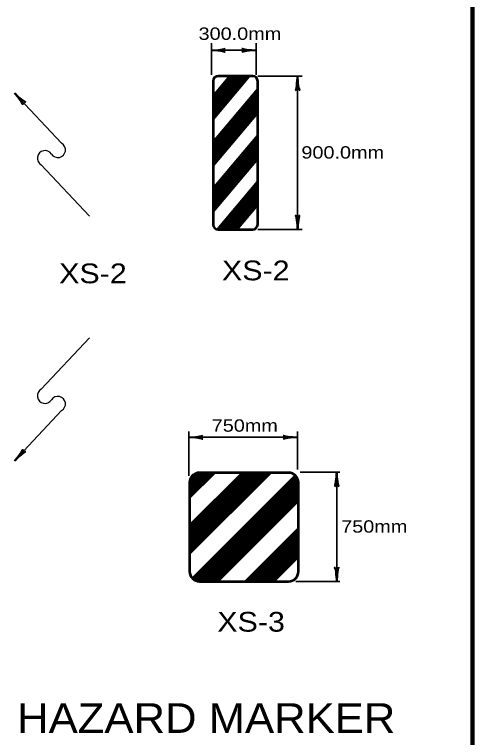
# Model space of a CAD drawing. Extents: x -1843 to -987, y 1073 to 1617.
# Drawn here: x -1105 to -993.8, y 1298.6 to 1474.2 of the extents above; entities that cross this region are included whole.
import ezdxf
from ezdxf.enums import TextEntityAlignment as Align

# ---------------------------------------------------------------- set-up
doc = ezdxf.new("R2010")
doc.units = 0
doc.header["$LTSCALE"] = 1.2
doc.layers.add('1', color=7, linetype='Continuous', lineweight=53)

msp = doc.modelspace()

# ---------------------------------------------------------------- linework, layer by layer
at = {"layer": '1', "lineweight": 158}
msp.add_line((-993.822, 1084.318), (-993.822, 1610.418), dxfattribs=at)
at = {"layer": '1', "lineweight": 13}
msp.add_line((-993.822, 1084.318), (-993.822, 1610.418), dxfattribs=at)
at = {"layer": '1', "lineweight": 35}
for p, q in [((-1057.149, 1459.516), (-1057.149, 1467.22)), ((-1046.35, 1459.516), (-1046.35, 1467.22)), ((-1057.284, 1465.455), (-1046.348, 1465.455)), ((-1045.947, 1459.178), (-1035.2, 1459.178)), ((-1036.297, 1459.178), (-1036.297, 1421.993)), ((-1045.947, 1421.978), (-1035.2, 1421.978)), ((-1062.693, 1372.873), (-1062.693, 1362.126)), ((-1036.293, 1372.873), (-1036.293, 1363.643)), ((-1062.774, 1371.497), (-1036.364, 1371.497)), ((-1035.674, 1363.034), (-1026.044, 1363.034)), ((-1026.785, 1363.039), (-1026.785, 1336.543)), ((-1036.748, 1336.504), (-1026.001, 1336.504))]:
    msp.add_line(p, q, dxfattribs=at)
at = {"layer": '1'}
for p, q in [((-1056.781, 1454.325), (-1052.713, 1459.172)), ((-1056.772, 1454.318), (-1052.705, 1459.165)), ((-1056.772, 1448.717), (-1048.005, 1459.165)), ((-1056.772, 1453.902), (-1052.356, 1459.165)), ((-1056.772, 1453.767), (-1052.243, 1459.165)), ((-1056.772, 1453.417), (-1051.949, 1459.165)), ((-1056.772, 1452.986), (-1051.587, 1459.165)), ((-1056.772, 1452.69), (-1051.339, 1459.165)), ((-1056.772, 1452.34), (-1051.045, 1459.165)), ((-1056.772, 1451.761), (-1050.56, 1459.165)), ((-1056.772, 1451.613), (-1050.435, 1459.165)), ((-1056.772, 1451.237), (-1050.12, 1459.165)), ((-1056.772, 1450.7), (-1049.669, 1459.165)), ((-1056.772, 1450.324), (-1049.353, 1459.165)), ((-1056.772, 1450.028), (-1049.105, 1459.165)), ((-1056.772, 1449.517), (-1048.676, 1459.165)), ((-1056.772, 1449.019), (-1048.258, 1459.165)), ((-1056.772, 1449.803), (-1048.916, 1459.165)), ((-1056.772, 1449.937), (-1049.029, 1459.165)), ((-1056.772, 1450.072), (-1049.142, 1459.165)), ((-1056.772, 1451.082), (-1049.989, 1459.165)), ((-1056.772, 1451.365), (-1050.227, 1459.165)), ((-1056.772, 1451.943), (-1050.712, 1459.165)), ((-1056.772, 1453.194), (-1051.762, 1459.165)), ((-1056.772, 1454.04), (-1052.472, 1459.165)), ((-1056.772, 1453.622), (-1052.121, 1459.165)), ((-1056.772, 1453.272), (-1051.827, 1459.165)), ((-1056.772, 1452.4), (-1051.096, 1459.165)), ((-1056.772, 1452.185), (-1050.915, 1459.165)), ((-1056.772, 1452.05), (-1050.802, 1459.165)), ((-1056.772, 1450.841), (-1049.787, 1459.165)), ((-1056.772, 1449.336), (-1048.524, 1459.165)), ((-1056.635, 1454.203), (-1052.568, 1459.05)), ((-1056.562, 1454.142), (-1052.347, 1459.165)), ((-1056.516, 1454.103), (-1052.449, 1458.95)), ((-1056.51, 1454.098), (-1052.258, 1459.165)), ((-1047.172, 1459.165), (-1055.572, 1459.165)), ((-1055.221, 1453.016), (-1050.062, 1459.165)), ((-1056.772, 1453.153), (-1052.131, 1458.683)), ((-1056.772, 1452.979), (-1052.045, 1458.611)), ((-1056.772, 1457.965), (-1056.772, 1423.165)), ((-1056.098, 1453.753), (-1052.031, 1458.6)), ((-1055.967, 1453.642), (-1051.9, 1458.489)), ((-1055.828, 1453.525), (-1051.76, 1458.372)), ((-1055.828, 1453.525), (-1051.76, 1458.372)), ((-1055.794, 1453.497), (-1051.727, 1458.345)), ((-1054.821, 1452.68), (-1050.753, 1457.528)), ((-1054.416, 1452.341), (-1050.348, 1457.188)), ((-1054.319, 1452.259), (-1050.251, 1457.106)), ((-1045.972, 1423.165), (-1045.972, 1457.965)), ((-1056.772, 1443.116), (-1045.972, 1455.987)), ((-1056.772, 1442.708), (-1045.972, 1455.579)), ((-1056.772, 1442.486), (-1045.972, 1455.357)), ((-1054.177, 1452.14), (-1050.109, 1456.987)), ((-1056.772, 1442.089), (-1045.972, 1454.96)), ((-1056.772, 1441.91), (-1045.972, 1454.781)), ((-1056.772, 1441.557), (-1045.972, 1454.428)), ((-1056.772, 1441.325), (-1045.972, 1454.196)), ((-1056.772, 1441.112), (-1045.972, 1453.983)), ((-1056.772, 1440.794), (-1045.972, 1453.665)), ((-1056.772, 1440.566), (-1045.972, 1453.437)), ((-1056.772, 1440.249), (-1045.972, 1453.12)), ((-1056.772, 1439.945), (-1045.972, 1452.816)), ((-1056.772, 1439.637), (-1045.972, 1452.508)), ((-1056.772, 1439.372), (-1045.972, 1452.243)), ((-1056.772, 1439.074), (-1045.972, 1451.945)), ((-1056.772, 1438.716), (-1045.972, 1451.587)), ((-1056.772, 1438.481), (-1045.972, 1451.352)), ((-1056.772, 1438.083), (-1045.972, 1450.954)), ((-1056.772, 1437.774), (-1045.972, 1450.645)), ((-1056.772, 1437.516), (-1045.972, 1450.387)), ((-1056.772, 1431.915), (-1045.972, 1444.786)), ((-1056.772, 1431.715), (-1045.972, 1444.586)), ((-1056.772, 1431.48), (-1045.972, 1444.351)), ((-1056.772, 1431.225), (-1045.972, 1444.096)), ((-1056.772, 1431.077), (-1045.972, 1443.948)), ((-1056.772, 1430.855), (-1045.972, 1443.726)), ((-1056.772, 1430.565), (-1045.972, 1443.436)), ((-1056.772, 1430.384), (-1045.972, 1443.255)), ((-1056.772, 1430.162), (-1045.972, 1443.033)), ((-1056.772, 1429.866), (-1045.972, 1442.737)), ((-1056.772, 1429.651), (-1045.972, 1442.522)), ((-1056.772, 1429.315), (-1045.972, 1442.186)), ((-1056.772, 1429.012), (-1045.972, 1441.883)), ((-1056.772, 1428.763), (-1045.972, 1441.634)), ((-1056.772, 1428.615), (-1045.972, 1441.486)), ((-1056.772, 1428.376), (-1045.972, 1441.246)), ((-1056.772, 1428.205), (-1045.972, 1441.076)), ((-1056.772, 1428.057), (-1045.972, 1440.928)), ((-1056.772, 1427.876), (-1045.972, 1440.747)), ((-1056.772, 1427.728), (-1045.972, 1440.599)), ((-1056.772, 1427.494), (-1045.972, 1440.365)), ((-1056.772, 1427.177), (-1045.972, 1440.048)), ((-1056.772, 1427.029), (-1045.972, 1439.9)), ((-1056.772, 1426.921), (-1045.972, 1439.792)), ((-1056.772, 1426.706), (-1045.972, 1439.577)), ((-1056.772, 1426.558), (-1045.972, 1439.429)), ((-1056.772, 1426.315), (-1045.972, 1439.186)), ((-1055.722, 1421.965), (-1045.972, 1433.585)), ((-1055.584, 1421.965), (-1045.972, 1433.42)), ((-1055.471, 1421.965), (-1045.972, 1433.285)), ((-1055.443, 1421.965), (-1045.972, 1433.252)), ((-1055.262, 1421.965), (-1045.972, 1433.036)), ((-1055.205, 1421.965), (-1045.972, 1432.969)), ((-1054.991, 1421.965), (-1045.972, 1432.713)), ((-1054.838, 1421.965), (-1045.972, 1432.531)), ((-1054.776, 1421.965), (-1045.972, 1432.458)), ((-1054.657, 1421.965), (-1045.972, 1432.316)), ((-1054.539, 1421.965), (-1045.972, 1432.175)), ((-1054.477, 1421.965), (-1045.972, 1432.101)), ((-1054.448, 1421.965), (-1045.972, 1432.067)), ((-1054.42, 1421.965), (-1045.972, 1432.033)), ((-1054.328, 1421.965), (-1045.972, 1431.923)), ((-1054.144, 1421.965), (-1045.972, 1431.704)), ((-1054.06, 1421.965), (-1045.972, 1431.604)), ((-1053.913, 1421.965), (-1045.972, 1431.428)), ((-1053.777, 1421.965), (-1045.972, 1431.266)), ((-1053.658, 1421.965), (-1045.972, 1431.125)), ((-1053.539, 1421.965), (-1045.972, 1430.983)), ((-1053.387, 1421.965), (-1045.972, 1430.802)), ((-1053.263, 1421.965), (-1045.972, 1430.654)), ((-1053.048, 1421.965), (-1045.972, 1430.398)), ((-1052.93, 1421.965), (-1045.972, 1430.257)), ((-1052.749, 1421.965), (-1045.972, 1430.041)), ((-1052.568, 1421.965), (-1045.972, 1429.826)), ((-1052.334, 1421.965), (-1045.972, 1429.547)), ((-1052.235, 1421.965), (-1045.972, 1429.429)), ((-1052.116, 1421.965), (-1045.972, 1429.287)), ((-1051.902, 1421.965), (-1045.972, 1429.032)), ((-1051.693, 1421.965), (-1045.972, 1428.783)), ((-1051.484, 1421.965), (-1045.972, 1428.534)), ((-1051.303, 1421.965), (-1045.972, 1428.318)), ((-1051.151, 1421.965), (-1045.972, 1428.137)), ((-1051.023, 1421.965), (-1045.972, 1427.984)), ((-1055.572, 1421.965), (-1047.172, 1421.965)), ((-1062.489, 1356.873), (-1056.453, 1362.908)), ((-1062.489, 1350.084), (-1049.665, 1362.908)), ((-1062.489, 1343.296), (-1042.877, 1362.908)), ((-1062.489, 1357.129), (-1056.71, 1362.908)), ((-1062.489, 1357.281), (-1056.862, 1362.908)), ((-1062.489, 1357.332), (-1056.912, 1362.908)), ((-1062.489, 1357.45), (-1057.03, 1362.908)), ((-1062.489, 1356.977), (-1056.558, 1362.908)), ((-1062.489, 1360.402), (-1059.983, 1362.908)), ((-1062.489, 1360.267), (-1059.848, 1362.908)), ((-1062.489, 1360.149), (-1059.73, 1362.908)), ((-1062.489, 1360.031), (-1059.612, 1362.908)), ((-1062.489, 1359.947), (-1059.527, 1362.908)), ((-1062.489, 1359.829), (-1059.409, 1362.908)), ((-1062.489, 1359.727), (-1059.308, 1362.908)), ((-1062.489, 1359.576), (-1059.156, 1362.908)), ((-1062.489, 1359.474), (-1059.055, 1362.908)), ((-1062.489, 1359.457), (-1059.038, 1362.908)), ((-1062.489, 1359.373), (-1058.954, 1362.908)), ((-1062.489, 1359.289), (-1058.869, 1362.908)), ((-1062.489, 1359.188), (-1058.768, 1362.908)), ((-1062.489, 1359.086), (-1058.667, 1362.908)), ((-1062.489, 1358.968), (-1058.549, 1362.908)), ((-1062.489, 1358.85), (-1058.431, 1362.908)), ((-1062.489, 1358.631), (-1058.211, 1362.908)), ((-1062.489, 1358.698), (-1058.279, 1362.908)), ((-1062.489, 1358.445), (-1058.026, 1362.908)), ((-1062.489, 1358.496), (-1058.077, 1362.908)), ((-1062.489, 1358.276), (-1057.857, 1362.908)), ((-1062.489, 1358.192), (-1057.773, 1362.908)), ((-1062.489, 1357.99), (-1057.57, 1362.908)), ((-1062.489, 1358.057), (-1057.638, 1362.908)), ((-1062.489, 1357.855), (-1057.435, 1362.908)), ((-1062.489, 1357.905), (-1057.486, 1362.908)), ((-1062.489, 1357.736), (-1057.317, 1362.908)), ((-1062.489, 1357.551), (-1057.132, 1362.908)), ((-1062.489, 1357.635), (-1057.216, 1362.908)), ((-1062.489, 1349.472), (-1049.053, 1362.908)), ((-1062.489, 1349.776), (-1049.356, 1362.908)), ((-1062.489, 1349.202), (-1048.783, 1362.908)), ((-1062.489, 1348.999), (-1048.58, 1362.908)), ((-1062.489, 1348.797), (-1048.378, 1362.908)), ((-1062.489, 1348.493), (-1048.074, 1362.908)), ((-1062.489, 1348.257), (-1047.838, 1362.908)), ((-1062.489, 1347.92), (-1047.5, 1362.908)), ((-1062.489, 1347.616), (-1047.197, 1362.908)), ((-1062.489, 1347.447), (-1047.028, 1362.908)), ((-1062.489, 1347.278), (-1046.859, 1362.908)), ((-1062.489, 1346.874), (-1046.454, 1362.908)), ((-1062.489, 1346.604), (-1046.184, 1362.908)), ((-1062.489, 1346.334), (-1045.915, 1362.908)), ((-1062.489, 1346.097), (-1045.678, 1362.908)), ((-1062.489, 1345.929), (-1045.51, 1362.908)), ((-1062.489, 1345.659), (-1045.24, 1362.908)), ((-1062.489, 1345.423), (-1045.003, 1362.908)), ((-1062.489, 1345.051), (-1044.632, 1362.908)), ((-1062.489, 1344.815), (-1044.396, 1362.908)), ((-1062.489, 1344.343), (-1043.924, 1362.908)), ((-1062.489, 1343.87), (-1043.451, 1362.908)), ((-1062.489, 1343.702), (-1043.282, 1362.908)), ((-1062.489, 1343.432), (-1043.013, 1362.908)), ((-1062.489, 1344.039), (-1043.62, 1362.908)), ((-1062.489, 1344.68), (-1044.261, 1362.908)), ((-1062.489, 1344.478), (-1044.059, 1362.908)), ((-1062.489, 1347.009), (-1046.589, 1362.908)), ((-1062.489, 1345.254), (-1044.835, 1362.908)), ((-1062.488, 1360.538), (-1060.118, 1362.908)), ((-1062.48, 1360.715), (-1060.295, 1362.899)), ((-1062.458, 1360.888), (-1060.469, 1362.878)), ((-1062.43, 1361.034), (-1060.615, 1362.85)), ((-1062.381, 1361.219), (-1060.799, 1362.8)), ((-1062.327, 1361.374), (-1060.954, 1362.746)), ((-1062.233, 1361.586), (-1061.166, 1362.653)), ((-1062.017, 1361.937), (-1061.517, 1362.436)), ((-1038.489, 1362.908), (-1060.089, 1362.908)), ((-1061.786, 1337.211), (-1036.792, 1362.205)), ((-1061.639, 1337.076), (-1036.657, 1362.059)), ((-1061.544, 1337), (-1036.58, 1361.963)), ((-1061.444, 1336.927), (-1036.508, 1361.863)), ((-1061.172, 1336.767), (-1036.347, 1361.592)), ((-1060.933, 1336.661), (-1036.242, 1361.352)), ((-1060.738, 1336.597), (-1036.178, 1361.157)), ((-1060.528, 1336.549), (-1036.129, 1360.947)), ((-1060.136, 1336.509), (-1036.089, 1360.556)), ((-1062.489, 1360.508), (-1062.489, 1338.908)), ((-1059.791, 1336.508), (-1036.089, 1360.211)), ((-1059.705, 1336.508), (-1036.089, 1360.124)), ((-1059.446, 1336.508), (-1036.089, 1359.865)), ((-1059.101, 1336.508), (-1036.089, 1359.52)), ((-1058.842, 1336.508), (-1036.089, 1359.261)), ((-1058.497, 1336.508), (-1036.089, 1358.916)), ((-1036.089, 1338.908), (-1036.089, 1360.508)), ((-1058.065, 1336.508), (-1036.089, 1358.485)), ((-1057.979, 1336.508), (-1036.089, 1358.398)), ((-1057.634, 1336.508), (-1036.089, 1358.053)), ((-1057.202, 1336.508), (-1036.089, 1357.622)), ((-1056.943, 1336.508), (-1036.089, 1357.363)), ((-1056.512, 1336.508), (-1036.089, 1356.931)), ((-1056.253, 1336.508), (-1036.089, 1356.672)), ((-1055.821, 1336.508), (-1036.089, 1356.241)), ((-1055.7, 1336.508), (-1036.089, 1356.12)), ((-1048.912, 1336.508), (-1036.089, 1349.332)), ((-1048.732, 1336.508), (-1036.089, 1349.151)), ((-1048.128, 1336.508), (-1036.089, 1348.547)), ((-1047.61, 1336.508), (-1036.089, 1348.029)), ((-1047.092, 1336.508), (-1036.089, 1347.511)), ((-1046.919, 1336.508), (-1036.089, 1347.339)), ((-1046.574, 1336.508), (-1036.089, 1346.994)), ((-1046.315, 1336.508), (-1036.089, 1346.735)), ((-1045.797, 1336.508), (-1036.089, 1346.217)), ((-1045.711, 1336.508), (-1036.089, 1346.131)), ((-1045.539, 1336.508), (-1036.089, 1345.958)), ((-1045.107, 1336.508), (-1036.089, 1345.526)), ((-1044.934, 1336.508), (-1036.089, 1345.354)), ((-1044.417, 1336.508), (-1036.089, 1344.836)), ((-1043.918, 1338.302), (-1036.089, 1346.131)), ((-1043.899, 1336.508), (-1036.089, 1344.318)), ((-1043.467, 1336.508), (-1036.089, 1343.887)), ((-1043.208, 1336.508), (-1036.089, 1343.628)), ((-1043.035, 1336.508), (-1036.089, 1343.455)), ((-1042.518, 1336.508), (-1036.089, 1342.937)), ((-1042.124, 1336.508), (-1036.089, 1342.543)), ((-1060.089, 1336.508), (-1038.489, 1336.508))]:
    msp.add_line(p, q, dxfattribs=at)
at = {"layer": '1', "lineweight": 25}
for p, q in [((-1105.006, 1455.067), (-1093.581, 1442.868)), ((-1098.512, 1437.66), (-1086.804, 1425.158)), ((-1098.512, 1383.181), (-1086.804, 1395.683)), ((-1105.006, 1365.774), (-1093.581, 1377.973))]:
    msp.add_line(p, q, dxfattribs=at)
at = {"layer": '1'}
for centre, radius, start, end in [((-1055.572, 1457.965), 1.2, 90, 180), ((-1047.172, 1457.965), 1.2, 0, 90), ((-1055.572, 1423.165), 1.2, 180, 270), ((-1047.172, 1423.165), 1.2, 270, 0), ((-1060.089, 1360.508), 2.4, 90, 180), ((-1038.489, 1360.508), 2.4, 0, 90), ((-1060.089, 1338.908), 2.4, 180, 270), ((-1038.489, 1338.908), 2.4, 270, 0)]:
    msp.add_arc(centre, radius, start, end, dxfattribs=at)
at = {"layer": '1', "lineweight": 25}
for centre, start, end in [((-1094.493, 1441.262), 212.7048, 60.42531), ((-1097.6, 1439.266), 32.7048, 240.42531), ((-1097.6, 1381.575), 119.57469, 327.2952), ((-1094.493, 1379.579), 299.57469, 147.2952)]:
    msp.add_arc(centre, 1.847, start, end, dxfattribs=at)
at = {"layer": '1', "lineweight": 40}
for centre, major_axis, ratio, start_param, end_param in [((-1055.975, 1465.786), (-2.143, -0.187), 0.122415, 0.8963533, 3.1415927), ((-1055.975, 1465.786), (-2.143, -0.187), 0.122415, 0.8963533, 3.1415927), ((-1047.693, 1465.708), (2.108, -0.211), 0.07063, 3.1407148, 5.41811), ((-1055.94, 1465.201), (2.108, -0.211), 0.07063, 6.2823074, 8.5597026), ((-1055.94, 1465.201), (2.108, -0.211), 0.07063, 6.2823074, 8.5597026), ((-1047.658, 1465.123), (2.143, 0.187), 0.122415, 0.8963533, 3.1415927), ((-1036.55, 1457.834), (-0.211, -2.108), 0.07063, 6.2823074, 8.5597026), ((-1035.965, 1457.869), (-0.187, 2.143), 0.122415, 0.8963533, 3.1415927), ((-1104.272, 1453.912), (-1.287, 1.683), 0.07063, 3.1407148, 5.41811), ((-1103.869, 1454.338), (-1.601, 1.436), 0.122415, 0.8963533, 3.1415927), ((-1036.628, 1423.303), (0.187, -2.143), 0.122415, 0.8963533, 3.1415927), ((-1036.043, 1423.338), (0.211, 2.108), 0.07063, 6.2823074, 8.5597026), ((-1061.465, 1371.828), (-2.143, -0.187), 0.122415, 0.8963533, 3.1415927), ((-1061.429, 1371.243), (2.108, -0.211), 0.07063, 6.2823074, 8.5597026), ((-1037.674, 1371.165), (2.143, 0.187), 0.122415, 0.8963533, 3.1415927), ((-1037.709, 1371.751), (2.108, -0.211), 0.07063, 3.1407148, 5.41811), ((-1104.272, 1366.929), (1.287, 1.683), 0.07063, 4.006668, 6.2840632), ((-1103.869, 1366.503), (-1.601, -1.436), 0.122415, 3.1415927, 5.386832), ((-1027.039, 1361.694), (-0.211, -2.108), 0.07063, 6.2823074, 8.5597026), ((-1026.453, 1361.729), (-0.187, 2.143), 0.122415, 0.8963533, 3.1415927), ((-1027.116, 1337.852), (0.187, -2.143), 0.122415, 0.8963533, 3.1415927), ((-1026.531, 1337.888), (0.211, 2.108), 0.07063, 6.2823074, 8.5597026)]:
    msp.add_ellipse(centre, major_axis=major_axis, ratio=ratio, start_param=start_param, end_param=end_param, dxfattribs=at)

# ---------------------------------------------------------------- texts
at = {"layer": '1'}
for s, height, width, p in [('300.0mm', 3, 1.2, (-1050.287, 1467.993)), ('900.0mm', 3, 1.2, (-1025.332, 1439.166)), ('XS-2', 4.8, 1.15, (-1085.966, 1408.896)), ('XS-2', 4.8, 1.15, (-1046.447, 1409.606)), ('750mm', 3, 1.2, (-1049.106, 1372.857)), ('750mm', 3, 1.2, (-1017.678, 1348.348)), ('XS-3', 4.8, 1.15, (-1047.582, 1324.306)), ('HAZARD MARKER', 7.2, 1.1, (-1058.464, 1299.732))]:
    msp.add_text(s, height=height, dxfattribs=dict(at, width=width)).set_placement(p, align=Align.CENTER)

doc.saveas('drawing.dxf')
